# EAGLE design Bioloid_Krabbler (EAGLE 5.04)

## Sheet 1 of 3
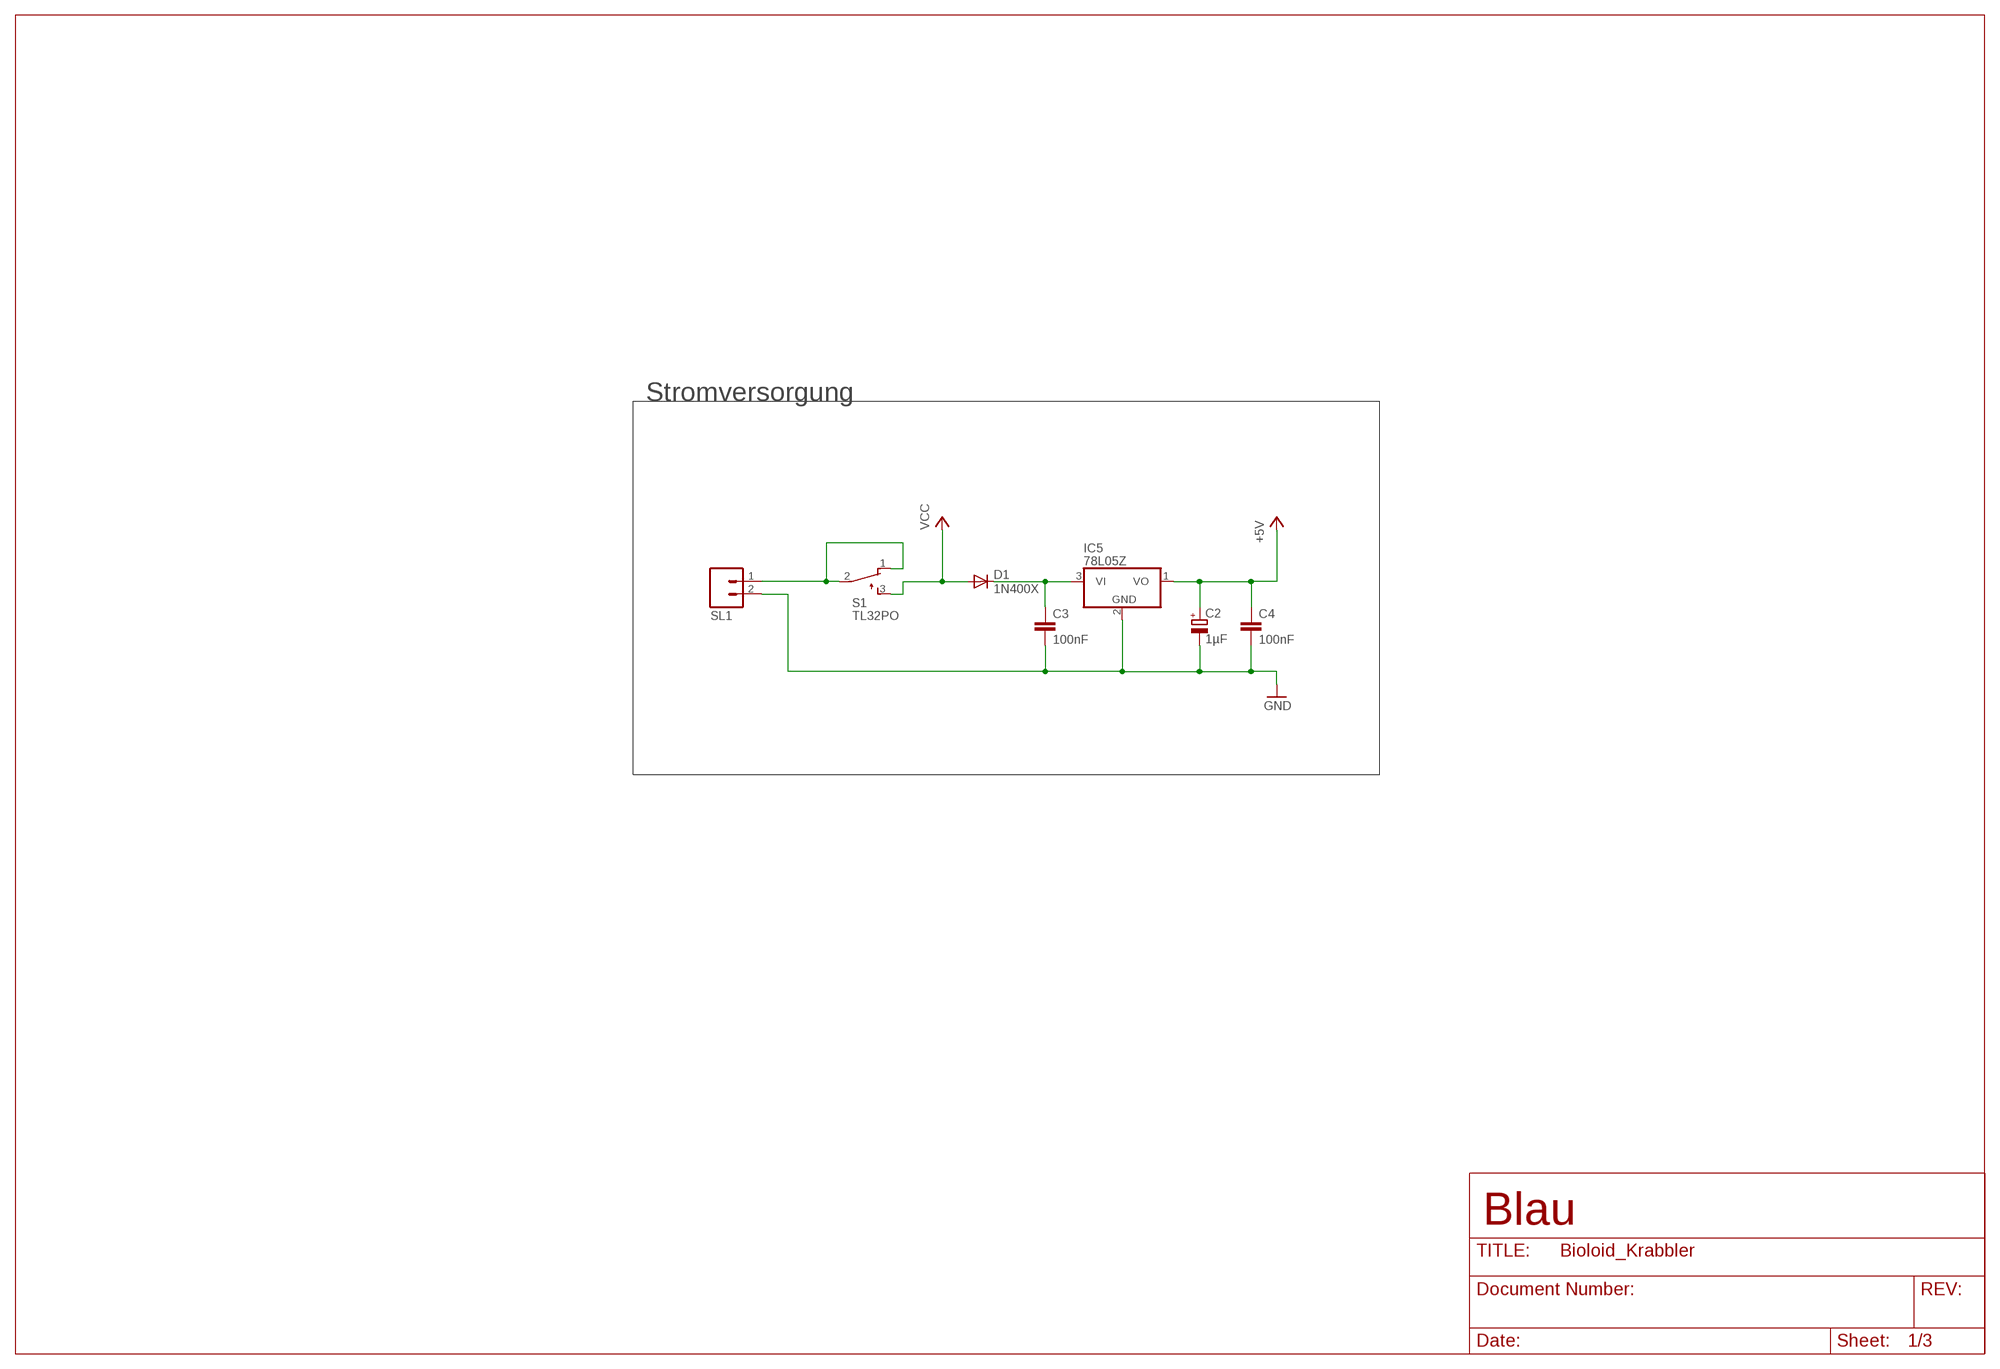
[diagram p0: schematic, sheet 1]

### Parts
C2  1µF  CPOL-EUE2.5-5  [E2,5-5]
C3  100nF  C-EUC0805  [C0805]
C4  100nF  C-EUC0805  [C0805]
D1  1N400X  1N4004  [DO41-10]
IC5  78L05Z  [TO92]
S1  TL32PO  [TL3XPO]
SL1  MA02  [02PA]

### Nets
+5V: C2.+ C4.1 IC5.1(VO) ; also sheet 2,3
GND: C2.- C3.2 C4.2 IC5.2(GND) SL1.2 ; also sheet 2,3
N$6: C3.1 D1.C IC5.3(VI)
N$9: S1.1(O) S1.2(P) SL1.1
VCC: D1.A S1.3(S) ; also sheet 2

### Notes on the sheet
- Stromversorgung
- Blau

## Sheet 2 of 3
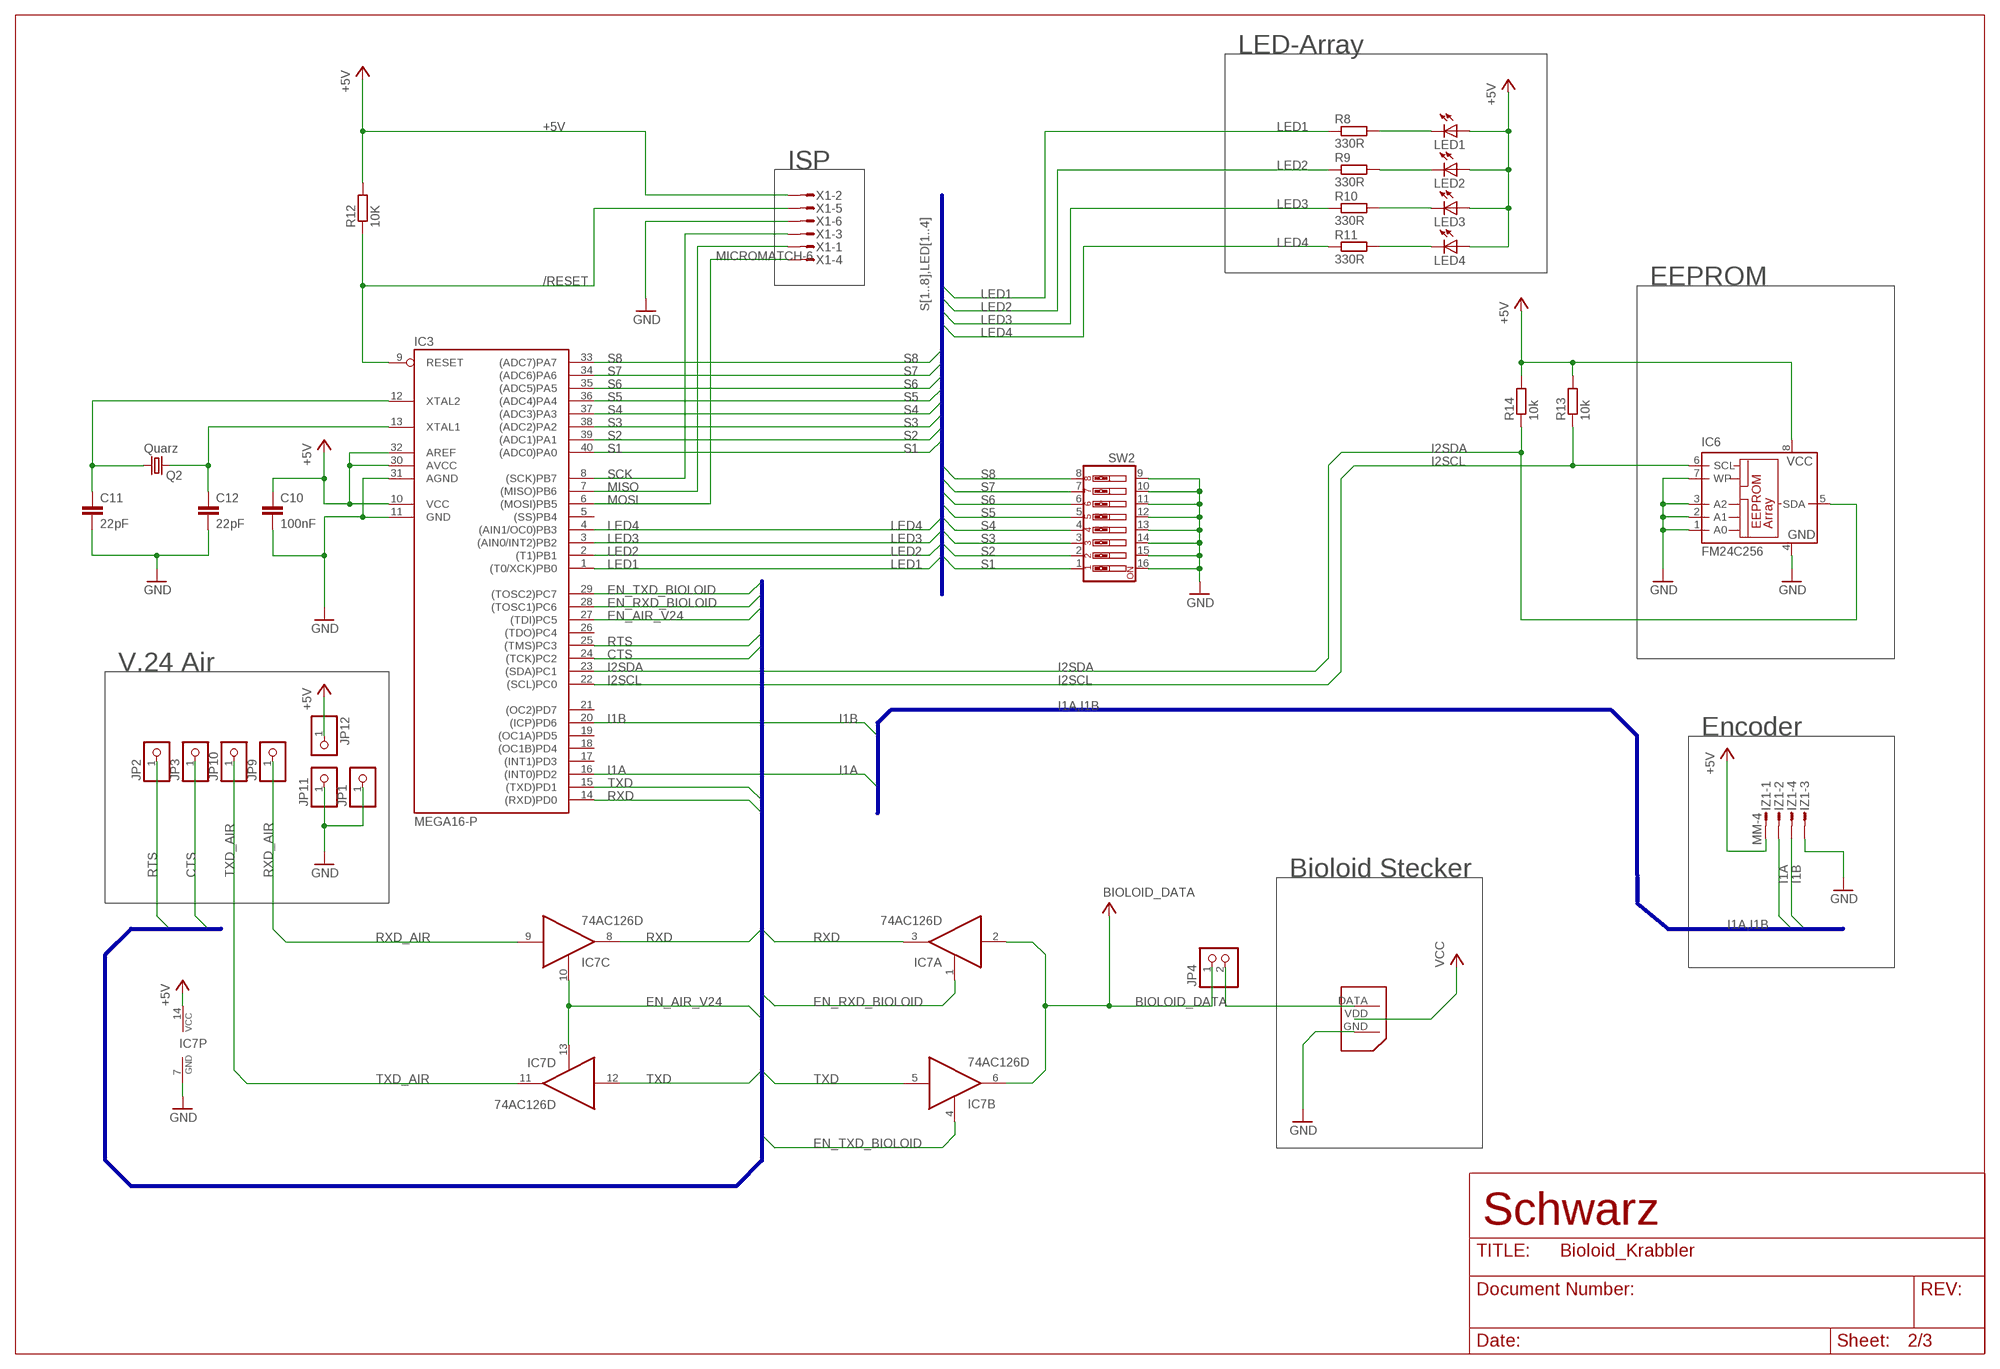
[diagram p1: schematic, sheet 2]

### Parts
C10  100nF  C-EUC0805  [C0805]
C11  22pF  C-EUC0805  [C0805]
C12  22pF  C-EUC0805  [C0805]
IC3  MEGA16-P  [DIL40]
IC6  FM24C256  24LC256SN  [SO-08]
IC7  74AC126D  [SO14]
IZ1  MM-4  MICROMATCH-4  [MICROMATCH-4]
JP1  PINHD-1X1  [1X01]
JP2  PINHD-1X1  [1X01]
JP3  PINHD-1X1  [1X01]
JP4  PINHD-1X2  [1X02]
JP9  PINHD-1X1  [1X01]
JP10  PINHD-1X1  [1X01]
JP11  PINHD-1X1  [1X01]
JP12  PINHD-1X1  [1X01]
LED1  grün  LED3MM  [LED3MM]
LED2  grün  LED3MM  [LED3MM]
LED3  grün  LED3MM  [LED3MM]
LED4  grün  LED3MM  [LED3MM]
Q2  Quarz  CRYSTALHC49S  [HC49/S]
R8  330R  R-EU_R1206  [R1206]
R9  330R  R-EU_R1206  [R1206]
R10  330R  R-EU_R1206  [R1206]
R11  330R  R-EU_R1206  [R1206]
R12  10K  R-EU_R1206  [R1206]
R13  10k  R-EU_R1206  [R1206]
R14  10k  R-EU_R1206  [R1206]
SW2  SW_DIP-8  [EDG-08]
U$2  BIOLOID_STECKER  [BIOLOID_BUCHSE]
X1  MICROMATCH-6  [MICROMATCH-6]

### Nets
+5V: C10.1 IC3.10(VCC) IC3.30(AVCC) IC3.32(AREF) IC6.8(VCC) IC7.14(P:VCC) IZ1.1 JP12.1 LED1.A LED2.A LED3.A LED4.A R12.2 R13.2 R14.2 X1.2 ; also sheet 1,3
/RESET: IC3.9(RESET) R12.1 X1.5
BIOLOID_DATA: IC7.2(A:I) IC7.6(B:O) JP4.1 ; also sheet 3
CTS: IC3.24((TCK)PC2) JP3.1
EN_AIR_V24: IC3.27((TDI)PC5) IC7.10(C:OE) IC7.13(D:OE)
EN_RXD_BIOLOID: IC3.28((TOSC1)PC6) IC7.1(A:OE)
EN_TXD_BIOLOID: IC3.29((TOSC2)PC7) IC7.4(B:OE)
GND: C10.2 C11.2 C12.2 IC3.11(GND) IC3.31(AGND) IC6.1(A0) IC6.2(A1) IC6.3(A2) IC6.4(GND) IC6.7(WP) IC7.7(P:GND) IZ1.3 JP1.1 JP11.1 SW2.9 SW2.10 SW2.11 SW2.12 SW2.13 SW2.14 SW2.15 SW2.16 U$2.GND X1.6 ; also sheet 1,3
I1A: IC3.16((INT0)PD2) IZ1.2
I1B: IC3.20((ICP)PD6) IZ1.4
I2SCL: IC3.22((SCL)PC0) IC6.6(SCL) R13.1
I2SDA: IC3.23((SDA)PC1) IC6.5(SDA) R14.1
LED1: IC3.1((T0/XCK)PB0) R8.1
LED2: IC3.2((T1)PB1) R9.1
LED3: IC3.3((AIN0/INT2)PB2) R10.1
LED4: IC3.4((AIN1/OC0)PB3) R11.1
MISO: IC3.7((MISO)PB6) X1.1
MOSI: IC3.6((MOSI)PB5) X1.4
N$1: LED4.K(C) R11.2
N$3: C12.1 IC3.13(XTAL1) Q2.1
N$7: C11.1 IC3.12(XTAL2) Q2.2
N$10: LED3.K(C) R10.2
N$11: LED2.K(C) R9.2
N$12: LED1.K(C) R8.2
N$14: JP4.2 U$2.DATA
RTS: IC3.25((TMS)PC3) JP2.1
RXD: IC3.14((RXD)PD0) IC7.3(A:O) IC7.8(C:O)
RXD_AIR: IC7.9(C:I) JP9.1
S1: IC3.40((ADC0)PA0) SW2.1
S2: IC3.39((ADC1)PA1) SW2.2
S3: IC3.38((ADC2)PA2) SW2.3
S4: IC3.37((ADC3)PA3) SW2.4
S5: IC3.36((ADC4)PA4) SW2.5
S6: IC3.35((ADC5)PA5) SW2.6
S7: IC3.34((ADC6)PA6) SW2.7
S8: IC3.33((ADC7)PA7) SW2.8
SCK: IC3.8((SCK)PB7) X1.3
TXD: IC3.15((TXD)PD1) IC7.5(B:I) IC7.12(D:I)
TXD_AIR: IC7.11(D:O) JP10.1
VCC: U$2.VDD ; also sheet 1
Unconnected: IC3.5((SS)PB4) IC3.17((INT1)PD3) IC3.18((OC1B)PD4) IC3.19((OC1A)PD5) IC3.21((OC2)PD7) IC3.26((TDO)PC4)

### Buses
S[1..8],LED[1..4]
I1A,I1B
TXD,RXD,RTS,CTS,EN_TXD_BIOLOID,EN_RXD_BIOLOID,EN_AIR_V24

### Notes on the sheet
- LED-Array
- ISP
- EEPROM
- V.24 Air
- Encoder
- Bioloid Stecker
- Schwarz

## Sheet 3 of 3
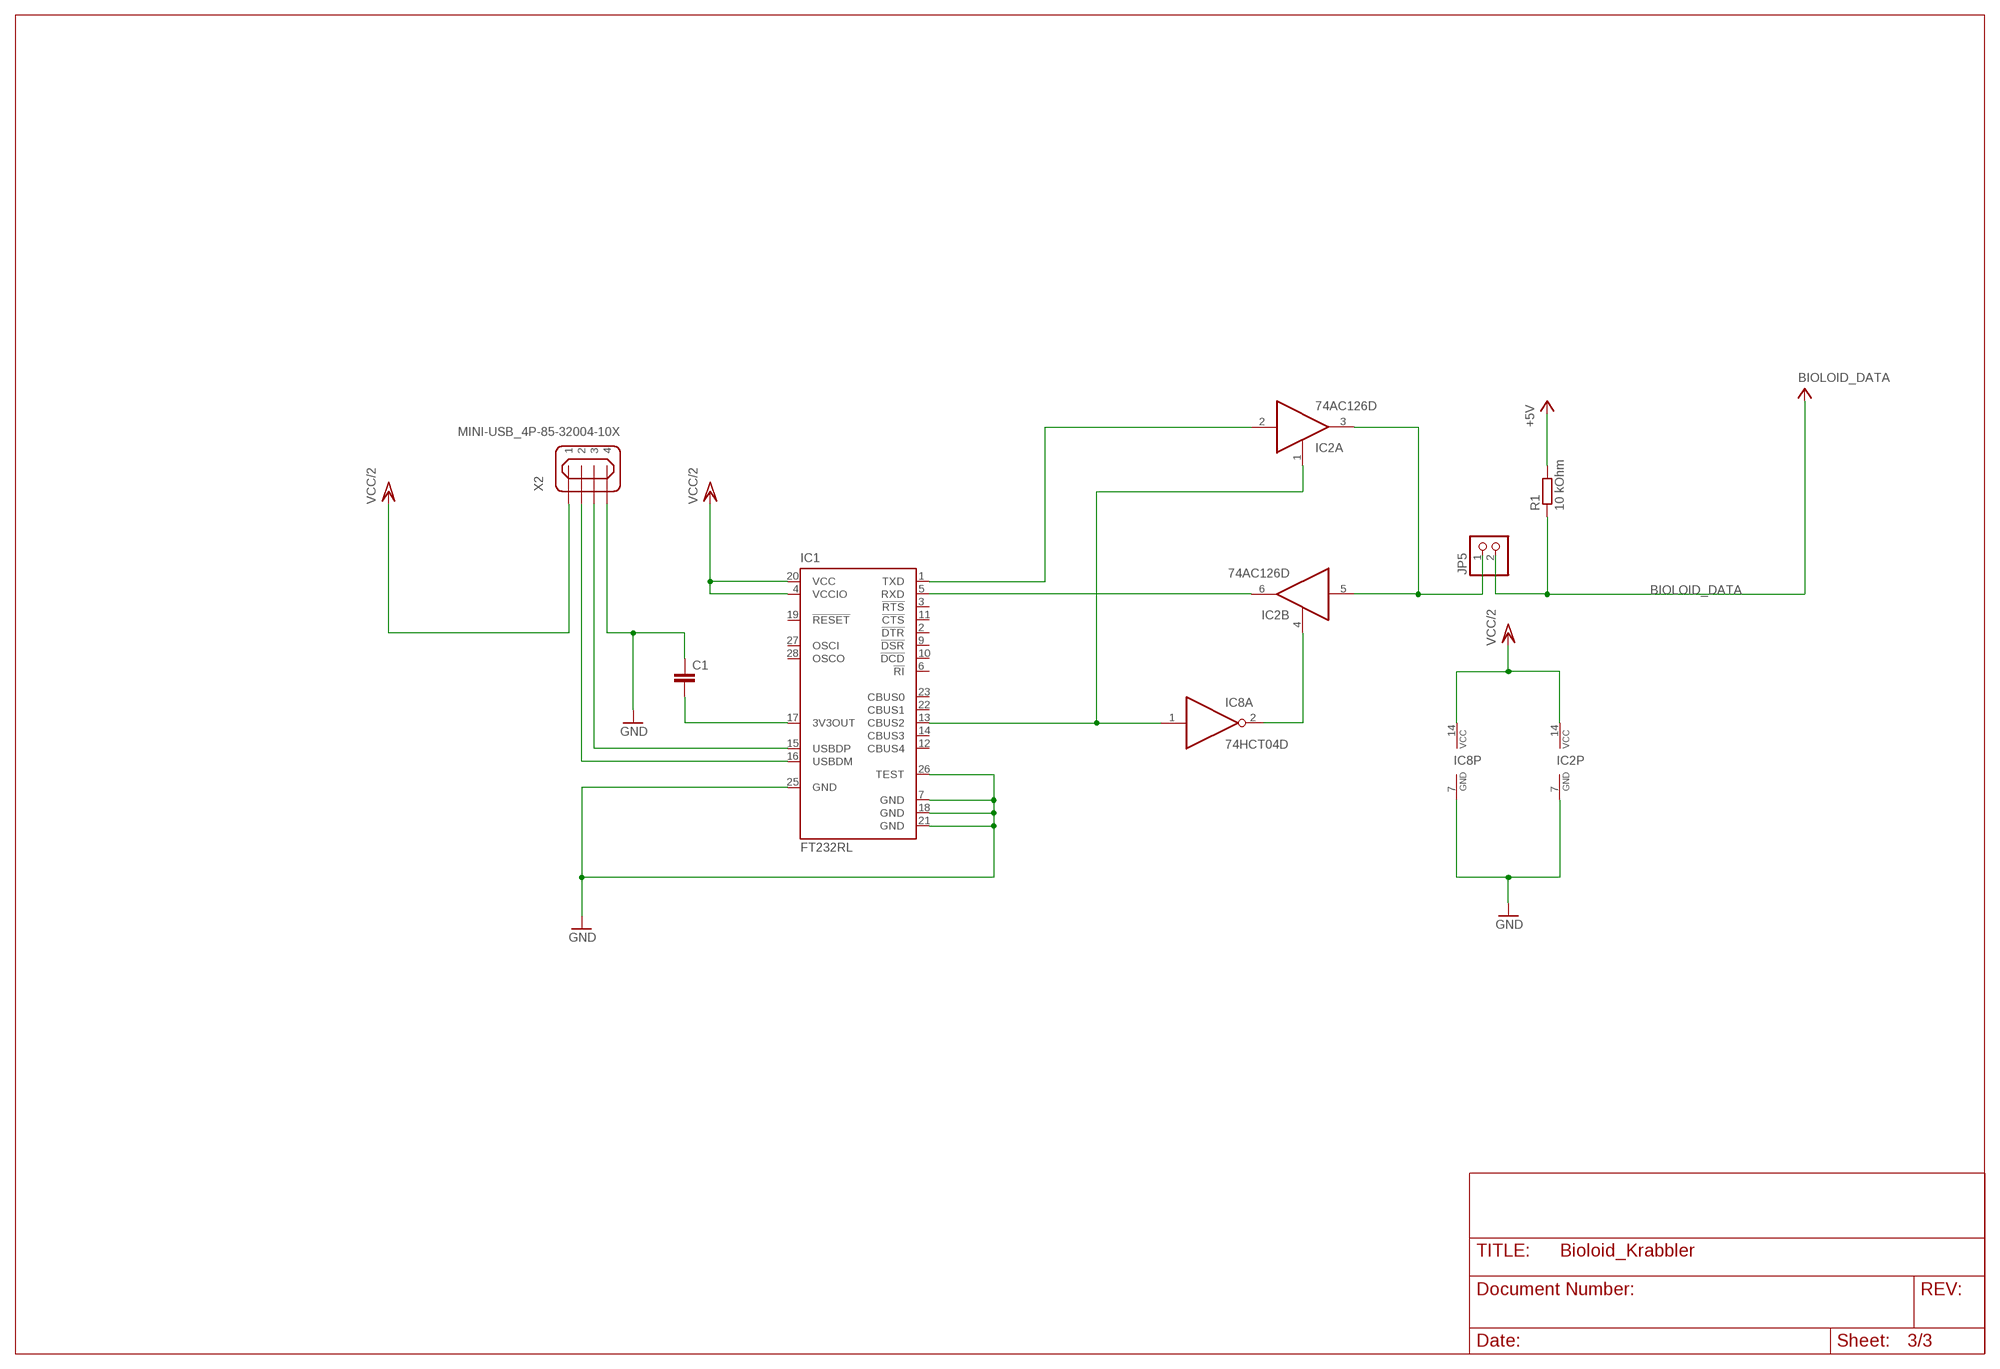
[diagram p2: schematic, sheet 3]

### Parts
C1  C-EUC0805  [C0805]
IC1  FT232RL  [SSOP28]
IC2  74AC126D  [SO14]
IC8  74HCT04D  [SO14]
JP5  PINHD-1X2  [1X02]
R1  10 kOhm  R-EU_M1206  [M1206]
X2  MINI-USB_4P-85-32004-10X  [85-32004-10X]

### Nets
+5V: R1.2 ; also sheet 1,2
BIOLOID_DATA: JP5.2 R1.1 ; also sheet 2
GND: C1.1 IC1.7(GND) IC1.18(GND) IC1.21(GND) IC1.25(GND) IC1.26(TEST) IC2.7(P:GND) IC8.7(P:GND) X2.4 ; also sheet 1,2
N$2: IC1.15(USBDP) X2.3
N$4: IC1.16(USBDM) X2.2
N$5: C1.2 IC1.17(3V3OUT)
N$8: IC1.1(TXD) IC2.2(A:I)
N$13: IC1.5(RXD) IC2.6(B:O)
N$15: IC1.13(CBUS2) IC2.1(A:OE) IC8.1(A:I)
N$16: IC2.4(B:OE) IC8.2(A:O)
N$17: IC2.3(A:O) IC2.5(B:I) JP5.1
VCC/2: IC1.4(VCCIO) IC1.20(VCC) IC2.14(P:VCC) IC8.14(P:VCC) X2.1
Unconnected: IC1.2(!DTR) IC1.3(!RTS) IC1.6(!RI) IC1.9(!DSR) IC1.10(!DCD) IC1.11(!CTS) IC1.12(CBUS4) IC1.14(CBUS3) IC1.19(!RESET) IC1.22(CBUS1) IC1.23(CBUS0) IC1.27(OSCI) IC1.28(OSCO) IC2.8(C:O) IC2.9(C:I) IC2.10(C:OE) IC2.11(D:O) IC2.12(D:I) IC2.13(D:OE) IC8.3(B:I) IC8.4(B:O) IC8.5(C:I) IC8.6(C:O) IC8.8(D:O) IC8.9(D:I) IC8.10(E:O) IC8.11(E:I) IC8.12(F:O) IC8.13(F:I)

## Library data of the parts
C1 C3 C4 C10-C12 = rcl:C-EU: CAPACITOR, European symbol
C2 = rcl:CPOL-EU: POLARIZED CAPACITOR, European symbol
D1 = diode:1N4004: DIODE
IC1 = ftdichip:FT232R: Source: http://www.ftdichip.com/Documents/DataSheets/DS_FT232R_v104.pdf
IC2 IC7 = 74xx-eu:74*126: Quad bus BUFFER, 3-state
IC3 = atmel:MEGA16-P: MICROCONTROLLER 16 Kbytes FLASH 1 kbytes SRAM 512 bytes EEPROM USART 8-channel 10 bit ADC Source: avr.lbr
IC5 = linear:78*: Positive VOLTAGE REGULATOR Source: http://cache.national.com/ds/LM/LM78L05.pdf http://www.fairchildsemi.com/ds/LM/LM7805.pdf
IC6 = microchip:24*: Serial EEPROM I2C
IC8 = 74xx-eu:74*04: Hex INVERTER
IZ1 = con-amp-micromatch:MICROMATCH-4: MicroMaTch 4 7-215464-4 / 0-215464-4 Drawing Number C-215464 DDEController.pdf
JP1-JP3 JP9-JP12 = pinhead:PINHD-1X1: PIN HEADER
JP4 JP5 = pinhead:PINHD-1X2: PIN HEADER
LED1-LED4 = led:LED: LED
Q2 = crystal:CRYSTAL: CRYSTAL
R1 R8-R14 = rcl:R-EU_: RESISTOR, European symbol
S1 = switch:TL32PO: TINY SWITCH ON - MOM Source: http://www2.produktinfo.conrad.com/datenblaetter/700000-724999/705152-da-01-de-Subminiaturschalter_TL_36YO.pdf
SL1 = con-amp-quick:MA02: AMP QUICK CONNECTOR
SW2 = special:SW_DIP-8: DIP SWITCH
U$2 = stecker_fessler:BIOLOID_STECKER
X1 = con-amp-micromatch:MICROMATCH-6: MicroMaTch 6 7-215464-6 / 0-215464-6 Drawing Number C-215464 DDEController.pdf
X2 = con-cypressindustries:MINI-USB_4P-: MINI USB 4 Pol. Source: www.cypressindustries.com

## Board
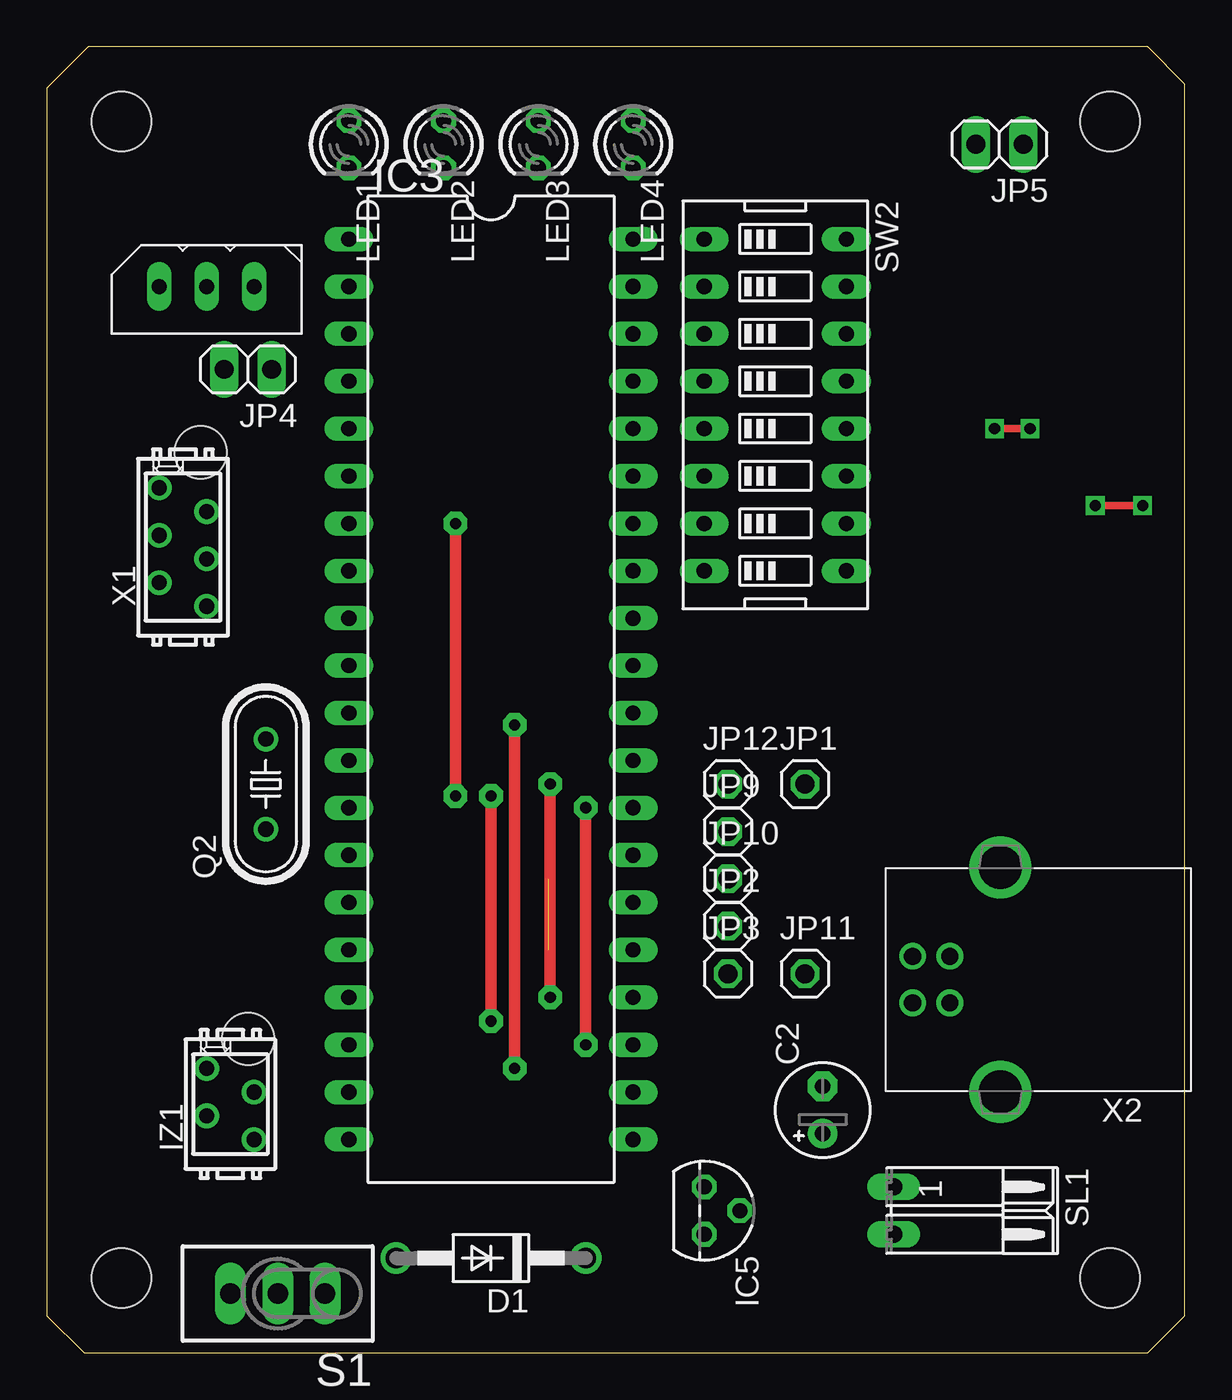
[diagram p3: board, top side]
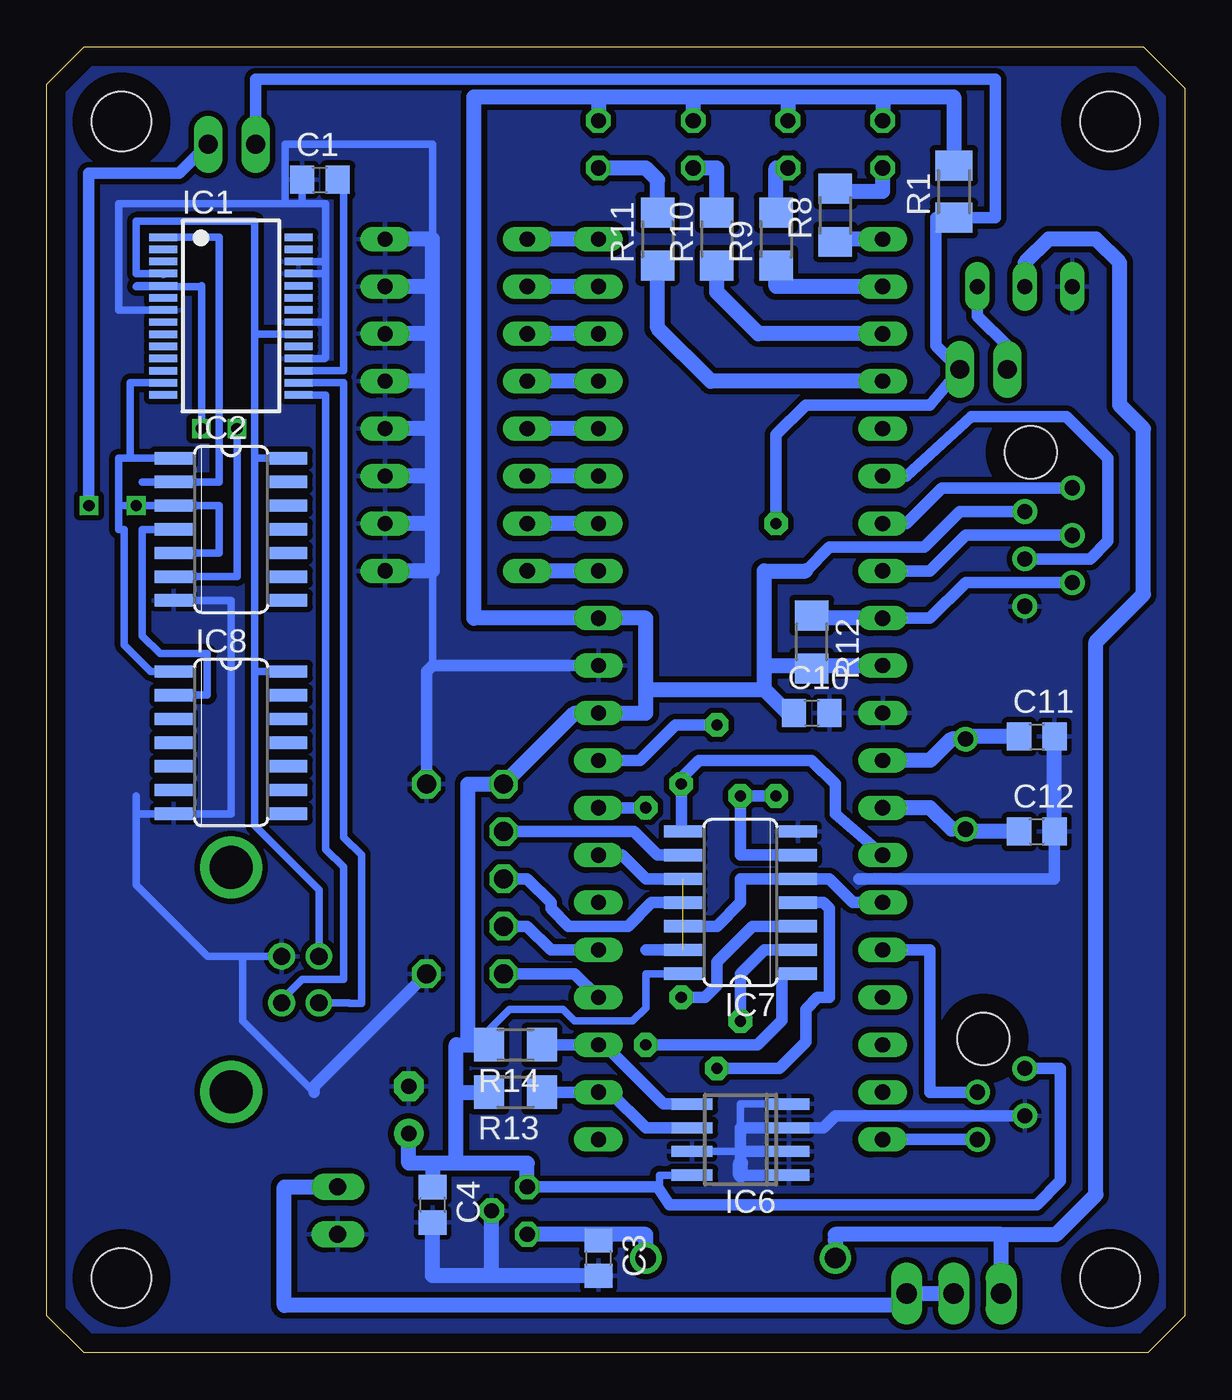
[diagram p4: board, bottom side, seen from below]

Size 61 x 70 mm. Coordinates in mm from the lower left corner, seen from the top.
Outline: 59,0 61,2 61,68 59,70 2.24,70 0,67.76 0,2 2,0 59,0
Copper layers (1*16): Top 0.035mm / dielectric 1.5mm / Bottom 0.035mm
Design rules "default": minimum track width 10mil, minimum drill 24mil, track to track 8mil, track to pad 8mil, pad to pad 8mil, via to via 8mil, smd to smd 8mil, copper to edge 40mil, drill to drill 8mil, minimum pad ring 10mil, minimum via ring 8mil, stop-mask expansion 4mil, vias tented up to drill 0mil, thermal gap 10mil
Holes 2.8 mm at 8.26,48.26 10.79,16.83
Holes 3.2 mm at 4,4 57,4 57,66 4,66

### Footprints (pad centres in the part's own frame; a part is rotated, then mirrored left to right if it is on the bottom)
C0805 = smd 1.3 x 1.5: 1 -0.95,0; 2 0.95,0
E2,5-5 = drill 0.813 pad 1.6 round: + -1.27,0 | drill 0.813 pad 1.6 octagon: - 1.27,0
DO41-10 = drill 1.118 round: A 5.08,0; C -5.08,0
SSOP28 = smd 0.4 x 1.5: 1 -4.225,-3.625; 2 -3.575,-3.625; 3 -2.925,-3.625; 4 -2.275,-3.625; 5 -1.625,-3.625; 6 -0.975,-3.625; 7 -0.325,-3.625; 8 0.325,-3.625; 9 0.975,-3.625; 10 1.625,-3.625; 11 2.275,-3.625; 12 2.925,-3.625; 13 3.575,-3.625; 14 4.225,-3.625; 15 4.225,3.625; 16 3.575,3.625; 17 2.925,3.625; 18 2.275,3.625; 19 1.625,3.625; 20 0.975,3.625; 21 0.325,3.625; 22 -0.325,3.625; 23 -0.975,3.625; 24 -1.625,3.625; 25 -2.275,3.625; 26 -2.925,3.625; 27 -3.575,3.625; 28 -4.225,3.625
SO14 = smd 0.66 x 2.032: 1 -3.81,-3.073; 2 -2.54,-3.073; 3 -1.27,-3.073; 4 0,-3.073; 5 1.27,-3.073; 6 2.54,-3.073; 7 3.81,-3.073; 8 3.81,3.073; 9 2.54,3.073; 10 1.27,3.073; 11 0,3.073; 12 -1.27,3.073; 13 -2.54,3.073; 14 -3.81,3.073
DIL40 = drill 0.813 long: 1 -24.13,-7.62; 2 -21.59,-7.62; 3 -19.05,-7.62; 4 -16.51,-7.62; 5 -13.97,-7.62; 6 -11.43,-7.62; 7 -8.89,-7.62; 8 -6.35,-7.62; 9 -3.81,-7.62; 10 -1.27,-7.62; 11 1.27,-7.62; 12 3.81,-7.62; 13 6.35,-7.62; 14 8.89,-7.62; 15 11.43,-7.62; 16 13.97,-7.62; 17 16.51,-7.62; 18 19.05,-7.62; 19 21.59,-7.62; 20 24.13,-7.62; 21 24.13,7.62; 22 21.59,7.62; 23 19.05,7.62; 24 16.51,7.62; 25 13.97,7.62; 26 11.43,7.62; 27 8.89,7.62; 28 6.35,7.62; 29 3.81,7.62; 30 1.27,7.62; 31 -1.27,7.62; 32 -3.81,7.62; 33 -6.35,7.62; 34 -8.89,7.62; 35 -11.43,7.62; 36 -13.97,7.62; 37 -16.51,7.62; 38 -19.05,7.62; 39 -21.59,7.62; 40 -24.13,7.62
TO92 = drill 0.813 octagon: 1 -1.27,0; 2 0,1.905; 3 1.27,0
SO-08 = smd 0.6 x 2.2: 1 -1.905,-2.6; 2 -0.635,-2.6; 3 0.635,-2.6; 4 1.905,-2.6; 5 1.905,2.6; 6 0.635,2.6; 7 -0.635,2.6; 8 -1.905,2.6
MICROMATCH-4 = drill 0.813 round: 1 1.905,1.27; 2 0.635,-1.27; 3 -0.635,1.27; 4 -1.905,-1.27
1X01 = drill 1.016 octagon: 1 0,0
1X02 = drill 1.016 long: 1 -1.27,0; 2 1.27,0
LED3MM = drill 0.813 octagon: A -1.27,0; K 1.27,0
HC49/S = drill 0.813 round: 1 -2.413,0; 2 2.413,0
M1206 = smd 1.6 x 2: 1 -1.4,0; 2 1.4,0
R1206 = smd 1.6 x 1.803: 1 -1.422,0; 2 1.422,0
TL3XPO = drill 1.1 pad 1.422 long: 1 -2.54,0; 2 0,0; 3 2.54,0
02PA = drill 0.914 long: 1 -1.27,0; 2 1.27,0
EDG-08 = drill 0.813 long: 1 -8.89,-3.81; 2 -6.35,-3.81; 3 -3.81,-3.81; 4 -1.27,-3.81; 5 1.27,-3.81; 6 3.81,-3.81; 7 6.35,-3.81; 8 8.89,-3.81; 9 8.89,3.81; 10 6.35,3.81; 11 3.81,3.81; 12 1.27,3.81; 13 -1.27,3.81; 14 -3.81,3.81; 15 -6.35,3.81; 16 -8.89,3.81
BIOLOID_BUCHSE = drill 0.8 long: DATA 0,-2.54; GND 0,2.54; VDD 0,0
MICROMATCH-6 = drill 0.813 round: 1 3.175,1.27; 2 1.905,-1.27; 3 0.635,1.27; 4 -0.635,-1.27; 5 -1.905,1.27; 6 -3.175,-1.27
85-32004-10X = drill 0.92 pad 1.27 round: 1 4.71,-1.25; 2 4.71,1.25; 3 2.71,1.25; 4 2.71,-1.25 | drill 2.3 pad 3 round: M1 0,6.02; M2 0,-6.02

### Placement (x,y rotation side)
C1  46.35,62.87 0 bottom
C2  41.59,13.02 90 top
C3  31.43,5.08 270 bottom
C4  40.32,7.94 270 bottom
C10  20,34.29 0 bottom
C11  7.94,33.02 0 bottom
C12  7.94,27.94 0 bottom
D1  23.81,5.08 180 top
IC1  51.12,55.56 270 bottom
IC2  51.12,44.13 270 bottom
IC3  23.81,35.56 270 top
IC5  35.24,7.62 270 top
IC6  23.81,11.43 90 bottom
IC7  23.81,24.13 90 bottom
IC8  51.12,32.7 270 bottom
IZ1  9.84,13.34 90 top
JP1  40.64,30.48 0 top
JP2  36.51,22.86 0 top
JP3  36.51,20.32 0 top
JP4  10.79,52.7 180 top
JP5  51.07,64.77 180 top
JP9  36.51,27.94 0 top
JP10  36.51,25.4 0 top
JP11  40.64,20.32 0 top
JP12  36.51,30.48 0 top
LED1  16.19,64.77 270 top
LED2  21.27,64.77 270 top
LED3  26.35,64.77 270 top
LED4  31.43,64.77 270 top
Q2  11.75,30.48 90 top
R1  12.38,62.23 90 bottom
R8  18.73,60.96 90 bottom
R9  21.91,59.69 90 bottom
R10  25.08,59.69 90 bottom
R11  28.26,59.69 90 bottom
R12  20,38.1 270 bottom
R13  35.88,13.97 180 bottom
R14  35.88,16.51 180 bottom
S1  12.38,3.17 180 top
SL1  45.4,7.62 270 top
SW2  39.05,50.8 270 top
U$2  8.57,57.15 90 top
X1  7.3,43.18 90 top
X2  51.12,20 180 top

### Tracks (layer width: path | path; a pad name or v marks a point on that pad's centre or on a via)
+5V
  Bottom 0.406: IC7.14 28.89,20.32 28.89,18.49 29.6,17.78 32.7,17.78 33.34,18.41 36.2,18.41 37.3,17.31 R14.2 | IC6.8 28.16,9.53 28.16,8.74
  Bottom 0.61: IZ1.1 6.67,15.24 6.67,9.21 7.94,7.94 27.62,7.94 28.16,8.74 28.26,8.89 IC5.1 | X1.2 12.06,45.09 13.97,43.18 19.05,43.18 20.32,41.91
  Bottom 0.813: IC3.10 19.85,36.83 R12.2 20.15,36.83 22.54,36.83 | 28.89,35.56 28.89,34.29 IC3.30 32.7,34.29 JP12.1 38.42,30.48 38.42,16.51 | 28.89,35.56 28.89,39.37 IC3.32 38.1,39.37 38.1,67.31 31.43,67.31 | 21.27,67.31 16.19,67.31 | 21.27,67.31 LED2.A | 26.35,67.31 21.27,67.31 | 26.35,67.31 LED3.A | 31.43,67.31 26.35,67.31 | 31.43,67.31 LED4.A | 16.19,67.31 LED1.A | 16.19,67.31 12.38,67.31 R1.2 | 40.32,10.16 C4.1 | IC5.1 35.24,10.16 | 35.24,10.16 40.32,10.16 | 38.42,16.51 39.05,16.51 39.05,13.97 | 38.42,16.51 R14.2 | 39.05,13.97 R13.2 | 35.24,10.16 39.05,10.16 39.05,13.97 | 20.32,41.91 22.54,41.91 22.54,36.83 | C10.1 21.27,34.29 22.54,35.56 | 22.54,35.56 22.54,36.83 | 28.89,35.56 22.54,35.56 | C2.+ 41.59,10.16 40.32,10.16
/RESET
  Bottom 0.61: IC3.9 13.65,39.37 11.75,41.27 X1.5
  Bottom 0.813: R12.1 19.85,39.37 IC3.9
BIOLOID_DATA  (via drill 0.6 pad 1.27)
  Top 0.61: v23.81,17.78 v23.81,29.84 | v21.91,29.84 v21.91,44.45
  Bottom 0.61: IC7.6 23.81,26.67 v23.81,29.84 v21.91,29.84 | IC7.2 22.54,21.59 23.81,20.32 v23.81,17.78 | v21.91,44.45 21.91,49.21 20.32,50.8 13.65,50.8 JP4.1 13.34,53.98 13.34,60.83 R1.1 10.16,60.83 10.16,68.26 49.8,68.26 JP5.2
CTS
  Bottom 0.61: IC3.24 32.7,20.32 JP3.1
EN_AIR_V24  (1 unrouted)
  Bottom 0.61: IC7.13 28.89,21.59 | IC7.10 28.89,25.4 30.16,26.67 IC3.27
EN_RXD_BIOLOID  (via drill 0.6 pad 1.27)
  Top 0.61: v28.89,16.51 v28.89,29.21
  Bottom 0.61: v28.89,29.21 IC3.28 | IC7.1 21.59,20.32 21.59,17.82 22.9,16.51 v28.89,16.51
EN_TXD_BIOLOID  (via drill 0.6 pad 1.27)
  Top 0.61: v25.08,15.24 v25.08,33.66
  Bottom 0.61: IC7.4 19.37,24.13 19.05,23.81 19.05,19.05 19.68,19.05 20.32,18.41 20.32,16.66 21.74,15.24 v25.08,15.24 | IC3.29 29.21,31.75 27.3,33.66 v25.08,33.66
GND
  Bottom 0.406: 46.04,58.49 IC1.26 | 46.04,58.49 46.04,57.84 | 46.04,57.84 IC1.25 | 46.04,57.84 46.04,55.24 | 46.04,55.24 IC1.21 | 46.04,55.24 46.04,53.34 46.09,53.29 IC1.18 | 47.31,61.59 46.04,61.59 46.04,58.49 | 48.21,61.59 47.31,61.59 | 48.21,61.59 57.15,61.59 57.15,55.89 IC1.7 | IC2.7 51.12,40.32 51.12,28.89 IC8.7 56.2,28.89 | 56.2,28.89 56.2,25.08 52.37,21.25 X2.4 50.48,21.25 50.48,17.78 46.67,13.97 | C1.1 47.3,61.59 47.31,61.59 | 48.21,61.59 48.21,64.77 40.32,64.77 40.32,57.15 | 40.32,36.83 40.32,41.91 | 56.2,28.89 56.2,29.84 | IC6.7 23.81,10.79 23.81,10.16 | IC6.4 23.81,13.34 23.81,12.06
  Bottom 0.61: IC6.1 23.81,9.53 23.81,10.79 | 23.81,10.79 IC6.2 | 23.81,10.79 23.81,12.06 IC6.3 19.37,12.06 18.73,12.7 IZ1.3 | 17.46,25.4 6.99,25.4 C12.2 | JP1.1 40.64,36.51 40.32,36.83 IC3.31 | JP11.1 46.67,14.29 46.67,13.97
  Bottom 0.813: C12.2 C11.2 | SW2.16 40.32,59.69 40.32,57.15 | 40.32,44.45 40.32,41.91 SW2.9 | 40.32,44.45 40.32,46.99 | 40.32,46.99 40.32,49.53 | 40.32,49.53 40.32,52.07 | 40.32,52.07 40.32,54.61 | 40.32,54.61 40.32,57.15 | 40.32,44.45 SW2.10 | 40.32,46.99 SW2.11 | 40.32,49.53 SW2.12 | 40.32,52.07 SW2.13 | 40.32,54.61 SW2.14 | 40.32,57.15 SW2.15 | C3.2 37.15,4.13 | 37.15,4.13 IC5.2 | 37.15,4.13 40.32,4.13 C4.2 | 23.81,9.53 23.81,10.16
  pour Bottom (isolate 0.3): -0.59,69.85 61.64,69.85 61.64,0 -0.59,0
I1A
  Bottom 0.61: IC3.16 13.65,21.59 13.65,13.97 IZ1.2
I1B
  Bottom 0.61: IZ1.4 IC3.20
I2SCL
  Bottom 0.61: IC6.6 28.89,12.06 30.8,13.97 IC3.22 R13.1
I2SDA
  Bottom 0.61: R14.1 IC3.23 31.11,16.51 27.94,13.34 IC6.5
LED1
  Bottom 0.813: IC3.1 18.73,59.69 R8.1
LED2
  Bottom 0.813: R9.1 21.91,57.15 IC3.2
LED3
  Bottom 0.813: IC3.3 22.86,54.61 25.08,56.83 R10.1
LED4
  Bottom 0.813: IC3.4 25.4,52.07 28.26,54.93 R11.1
MISO
  Bottom 0.61: IC3.7 14.92,44.45 13.02,46.35 X1.1
MOSI
  Bottom 0.61: IC3.6 14.92,46.99 11.43,50.16 6.35,50.16 4.13,47.94 4.13,43.5 5.08,42.55 X1.4
N$1
  Bottom 0.813: LED4.K 28.89,63.5 28.26,62.87 R11.2
N$2
  Bottom 0.406: IC1.15 46.04,51.34 46.04,26.99 45.09,26.04 45.09,20 47.31,20 48.41,18.9 X2.3
N$3
  Bottom 0.813: IC3.13 13.65,29.21 12.51,28.07 Q2.1 11.62,27.94 C12.1
N$4
  Bottom 0.406: IC1.16 45.09,51.99 45.09,27.62 44.13,26.67 44.13,18.73 44.77,18.73 44.79,18.75 X2.2
N$5
  Bottom 0.406: IC1.17 45.09,52.64 45.09,62.87 C1.2
N$6
  Bottom 0.813: 31.43,6.35 IC5.3 | D1.C 28.89,6.35 31.43,6.35 | 31.43,6.35 C3.1
N$7
  Bottom 0.813: IC3.12 13.65,31.75 12.51,32.89 Q2.2 11.62,33.02 C11.1
N$8
  Bottom 0.406: 55.88,46.67 IC2.2 51.75,46.67 51.75,59.79 IC1.1
N$9
  Bottom 0.813: S1.2 S1.1 15.56,2.54 48.26,2.54 48.26,8.89 SL1.1
N$10
  Bottom 0.813: LED3.K 25.08,63.5 R10.2
N$11
  Bottom 0.813: R9.2 21.91,63.5 LED2.K
N$12
  Bottom 0.813: R8.2 18.73,62.23 16.19,62.23 LED1.K
N$13  (via drill 0.6)
  Top 0.406: v50.8,49.53 v52.7,49.53
  Bottom 0.406: v52.7,49.53 52.7,57.19 52.74,57.15 56.2,57.15 56.16,57.19 IC1.5 | IC2.6 50.8,41.59 v50.8,49.53
N$14
  Bottom 0.61: U$2.DATA 11.11,55.56 9.53,53.98 JP4.2
N$15
  Bottom 0.406: 56.52,47.94 IC2.1 | 56.52,47.94 56.52,51.99 IC1.13 | IC8.1 55.41,36.51 56.83,37.93 56.83,44.13 57.15,44.13 57.15,47.94 56.52,47.94
N$16
  Bottom 0.406: IC2.4 55.88,44.13 55.88,38.42 54.93,37.47 52.39,37.47 52.39,35.24 IC8.2
N$17  (via drill 0.6)
  Top 0.406: v56.2,45.4 v58.74,45.4
  Bottom 0.406: 51.75,45.4 51.75,42.86 IC2.5 | 51.75,45.4 IC2.3 55.88,45.4 | 51.75,45.4 v56.2,45.4 56.83,45.4
  Bottom 0.61: v58.74,45.4 58.74,63.22 53.89,63.22 JP5.1
RTS
  Bottom 0.61: IC3.25 33.97,21.59 35.24,22.86 JP2.1
RXD  (via drill 0.6 pad 1.27)
  Top 0.61: v26.99,30.48 v26.99,19.05
  Bottom 0.61: IC7.3 23.18,22.86 25.08,20.95 25.08,19.68 25.72,19.05 v26.99,19.05 | IC7.8 26.99,28.04 v26.99,30.48 26.99,30.8 26.04,31.75 20,31.75 18.73,30.48 18.73,28.89 IC3.14
RXD_AIR
  Bottom 0.61: IC7.9 28.26,26.67 29.53,27.94 JP9.1
S1
  Bottom 0.813: IC3.40 SW2.1
S2
  Bottom 0.813: IC3.39 SW2.2
S3
  Bottom 0.813: IC3.38 SW2.3
S4
  Bottom 0.813: IC3.37 SW2.4
S5
  Bottom 0.813: IC3.36 SW2.5
S6
  Bottom 0.813: IC3.35 SW2.6
S7
  Bottom 0.813: IC3.34 SW2.7
S8
  Bottom 0.813: IC3.33 SW2.8
SCK
  Bottom 0.61: IC3.8 13.65,41.91 11.75,43.81 X1.3
TXD
  Bottom 0.61: IC7.12 25.08,22.86 23.81,24.13 23.81,25.4 IC7.5 19.05,25.4 17.78,24.13 IC3.15
TXD_AIR
  Bottom 0.61: JP10.1 35.24,25.4 33.97,24.13 33.97,23.81 33.02,22.86 29.84,22.86 28.57,24.13 IC7.11
VCC
  Bottom 0.813: 9.84,6.35 18.73,6.35 18.73,6.03 D1.A | S1.3 9.84,6.35 | 9.84,6.35 6.89,6.35 4.76,8.48 4.76,38.1 2.22,40.64 2.22,49.53 3.49,50.8 3.49,58.42 4.76,59.69 7.3,59.69 8.57,58.42 U$2.VDD
VCC/2
  Bottom 0.406: 54.74,57.78 IC1.4 56.2,57.84 56.2,60.64 49.85,60.64 49.85,54.59 | 49.85,54.59 IC1.20 | 49.85,47.94 49.85,54.59 | 49.85,47.94 IC2.14 | 49.85,36.51 49.85,47.94 | 49.85,36.51 IC8.14 | 49.85,36.51 49.85,28.26 46.41,24.82 X2.1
